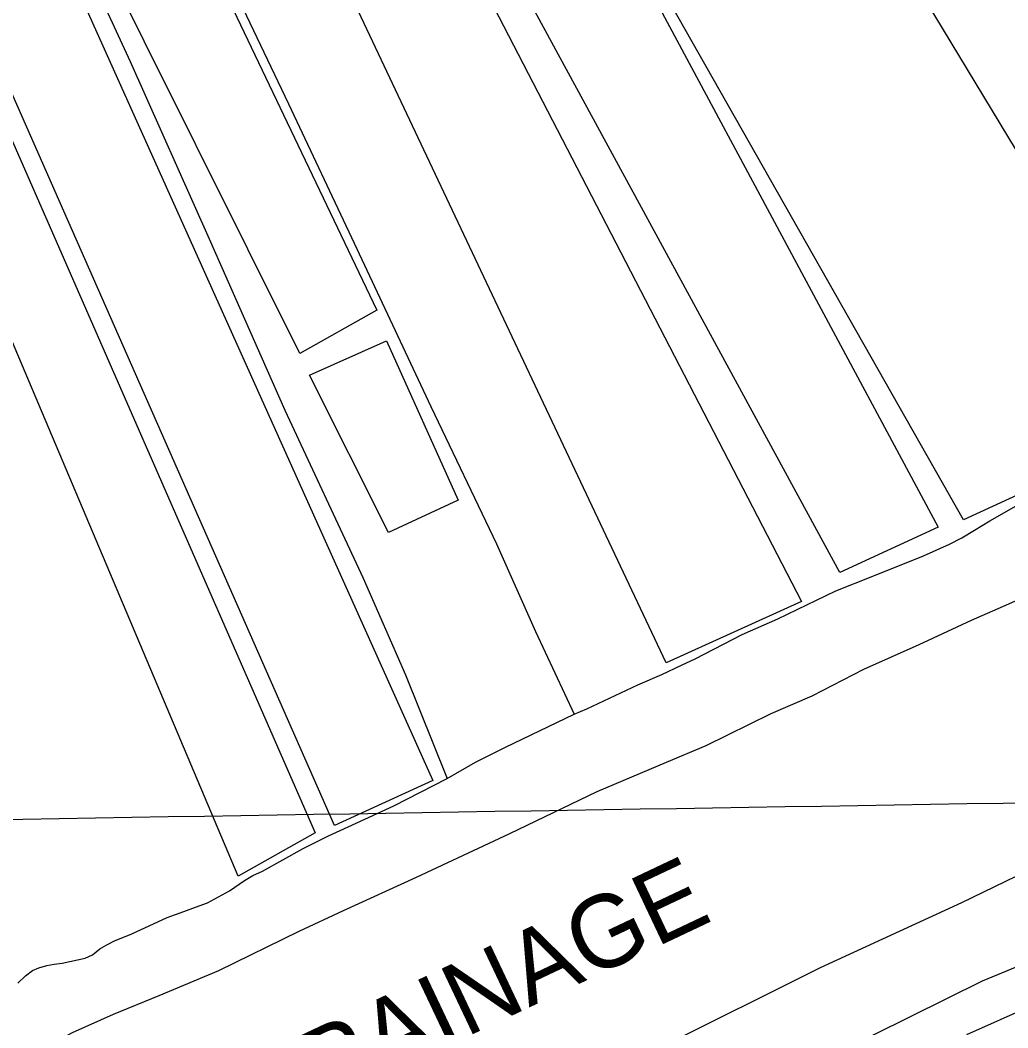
# Model space of a CAD drawing. Extents: x 3855477 to 3893699, y 299188 to 325115.
# Drawn here: x 3874161 to 3875290, y 307641 to 308792 of the extents above; entities that cross this region are included whole.
import ezdxf

# ---------------------------------------------------------------- set-up
doc = ezdxf.new("R2010")
doc.units = 0
for name, color, linetype in [('V-GRID-MAJR', 7, 'Continuous'), ('V-LEVE-TOET', 7, 'Continuous'), ('V-RIVR-IDEN', 7, 'Continuous'), ('V-ROAD-CNTR', 7, 'Continuous'), ('V-SITE-VEGE', 7, 'Continuous'), ('V-TOPO-SHOR', 7, 'Continuous'), ('V-WETL-SWMP', 7, 'Continuous')]:
    doc.layers.add(name, color=color, linetype=linetype)

msp = doc.modelspace()

# ---------------------------------------------------------------- linework, layer by layer
at = {"layer": 'V-GRID-MAJR'}
msp.add_spline([(3859685.5, 307646.8), (3864995.7, 307731.4), (3870305.8, 307816.8), (3875615.9, 307902.9), (3880925.9, 307989.8), (3886236, 308077.5), (3891546.1, 308165.9)], degree=3, dxfattribs=at)
at = {"layer": 'V-LEVE-TOET'}
for points in [[(3876530.2, 308840.7), (3876465.3, 308764.9), (3876379.5, 308663), (3876274, 308530.6), (3876148, 308385.2), (3876032.6, 308247.6), (3875890, 308078.7), (3875855.6, 308039.7), (3875839.5, 308020.5), (3875818.5, 308005.5), (3875774.1, 307973.9), (3875647.1, 307879.7), (3875592.7, 307843.7), (3875555.4, 307825.7), (3875416.7, 307758.7), (3875260, 307693.9), (3875094.8, 307612.1), (3874928, 307541.3), (3874799.7, 307469)], [(3874707.6, 307542.1), (3874890.7, 307617.4), (3875075.5, 307709.6), (3875236.9, 307783.7), (3875423.3, 307874.3), (3875534.2, 307924.8), (3875587.1, 307951.8), (3875621.4, 307975.1), (3875659.6, 308007.3), (3875684.5, 308022.2), (3875722.5, 308049.2), (3875775.6, 308092.4), (3875798.9, 308116), (3875841.3, 308167.8), (3875888.2, 308225.7), (3875931.6, 308273), (3875952.9, 308297.1), (3876000, 308349.5), (3876064.7, 308420.2), (3876115.4, 308483.5)]]:
    msp.add_lwpolyline(points, dxfattribs=at)
at = {"layer": 'V-ROAD-CNTR'}
for points in [[(3871246, 308430.1), (3871456.8, 308465.5), (3871756, 308526.8), (3872125.9, 308626.4), (3872419.4, 308717.8), (3872694.2, 308826.9), (3872951.4, 308943.1), (3873197.2, 309062.5), (3873396.1, 309173.9), (3873603.2, 309301.5), (3873850.1, 309473.5), (3874076.9, 309643.6), (3874288.2, 309821.2), (3874524.7, 310044.2), (3874666.7, 310183.4)], [(3871306.7, 308516.8), (3871483.4, 308547.2), (3871799.6, 308615), (3872141.2, 308709.5), (3872363.6, 308783.1), (3872623.5, 308880.1), (3872867.9, 308988.6), (3873088.8, 309092.9), (3873264.9, 309189.6), (3873489.8, 309319.8), (3873684.7, 309452.1), (3873900.8, 309605.6), (3874069.5, 309735.8), (3874209.4, 309855.6), (3874334.7, 309968.6), (3874503.8, 310129.8)]]:
    msp.add_spline(points, degree=3, dxfattribs=at)
at = {"layer": 'V-SITE-VEGE'}
for points in [[(3873883.7, 309272), (3873955.8, 309103.3), (3874023.8, 308947.5), (3874075.2, 308828), (3874498, 307863.4), (3874409.8, 307813.8), (3873992.2, 308800.8), (3873941.3, 308934.9), (3873894.5, 309047), (3873856.5, 309145), (3873817.9, 309230.8), (3873794.6, 309293), (3873783.4, 309323), (3873783.4, 309332.5), (3873785.8, 309340.1), (3873792.2, 309349.3), (3873804.2, 309359), (3873817.3, 309366.4), (3873824.6, 309369.7), (3873831.5, 309370), (3873836.6, 309368), (3873841.3, 309361)], [(3874347.1, 308924.5), (3874568.5, 308460.9), (3874480.3, 308411.3), (3874243.1, 308887.8), (3874222.2, 308929.8), (3874221.5, 308933.5), (3874222.2, 308937.9), (3874226.1, 308942.7), (3874292.4, 308976.7), (3874311.8, 308986.2), (3874315.6, 308986.7), (3874318, 308985.3)], [(3874661.1, 308243.8), (3874581.7, 308206.6), (3874491.4, 308386.5), (3874579.5, 308425.8)]]:
    msp.add_lwpolyline(points, close=True, dxfattribs=at)
for points in [[(3874916.8, 309275.1), (3875485.6, 308334.8), (3875238.7, 308221.1), (3874716.2, 309142.2)], [(3874886, 308816.5), (3875210, 308212.8), (3875097.6, 308161.1), (3874603.8, 309069.9)], [(3874573.7, 309055.5), (3875053.5, 308128), (3874899.2, 308057.7), (3874459.2, 308988.9)], [(3874202.8, 308879.5), (3874632.4, 307923.4), (3874520, 307871.7), (3874094.5, 308837.1)]]:
    msp.add_lwpolyline(points, dxfattribs=at)
at = {"layer": 'V-TOPO-SHOR'}
for points in [[(3874059.7, 309558.2), (3874162.5, 309345.8), (3874273, 309109.2), (3874383.2, 308873.3), (3874467.4, 308696.6), (3874542.3, 308537.5), (3874630.2, 308350.7), (3874705.1, 308193.8), (3874749.8, 308093.5), (3874793.8, 307999.1)], [(3873956.9, 309478.1), (3874034.2, 309308.8), (3874106.9, 309140.3), (3874194.3, 308944.9), (3874286.4, 308745.1), (3874376.6, 308542.4), (3874463.1, 308346.6), (3874552.7, 308154.6), (3874601.1, 308044), (3874648.6, 307925.7)], [(3874158.2, 307691.7), (3874166.7, 307700), (3874174.8, 307706.1), (3874182, 307709.3), (3874191, 307711.8), (3874199.6, 307713.4), (3874208.6, 307714.7), (3874235, 307720.1), (3874243.4, 307724.1), (3874251.7, 307730.8), (3874259.7, 307735.3), (3874269.4, 307740.3), (3874279.8, 307744.7), (3874288.2, 307748), (3874328.6, 307766.7), (3874347.7, 307773.7), (3874361.1, 307778.6), (3874374.7, 307783.6), (3874400, 307797.2), (3874417.2, 307809.1), (3874426.7, 307814.9), (3874437.5, 307819.6), (3874484, 307845.4), (3874513.2, 307859.9), (3874535.6, 307870.4), (3874587.7, 307894.5), (3874648.6, 307925.7), (3874681.2, 307944.2), (3874715.4, 307961.3), (3874793.8, 307999.1), (3874808.3, 308005), (3874866.6, 308032.6), (3874894.2, 308044.6), (3874916.6, 308055.2), (3874932.1, 308062.4), (3874985.8, 308090), (3875026.8, 308107.9), (3875093, 308140.2), (3875135.4, 308156.7), (3875193.1, 308180), (3875222.7, 308193.5), (3875237, 308200.6), (3875251.5, 308209.3), (3875268.8, 308220.1), (3875299.2, 308237)], [(3875321.3, 308138.6), (3875284, 308122), (3875247.7, 308106), (3875187.6, 308078.2), (3875124.5, 308050.1), (3875065.6, 308019.8), (3875018.7, 307999.3), (3874944.4, 307962.8), (3874899.1, 307944), (3874819.8, 307910.2), (3874719.8, 307862.4), (3874613.4, 307812.6), (3874530, 307774.5), (3874479.3, 307750.6), (3874387.4, 307705.6), (3874319, 307677.3), (3874267, 307656), (3874220, 307635), (3874192, 307619.7), (3874168.2, 307604.4), (3874145.8, 307586.6)]]:
    msp.add_lwpolyline(points, dxfattribs=at)
at = {"layer": 'V-WETL-SWMP'}
msp.add_line((3875449.7, 307725.9), (3875242.3, 307632.5), dxfattribs=at)

# ---------------------------------------------------------------- texts
at = {"layer": 'V-RIVR-IDEN'}
msp.add_text('DRAINAGE', height=83, rotation=25.3243, dxfattribs=at).set_placement((3874430.1, 307516))

doc.saveas('drawing.dxf')
